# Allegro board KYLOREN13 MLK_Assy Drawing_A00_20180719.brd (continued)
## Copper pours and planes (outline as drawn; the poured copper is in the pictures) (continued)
PWR_CHG_LGATE2 on TOP: 46.1,63.01 45.97,63.14 45.97,63.65 46.1,63.77 47.24,63.77 47.37,63.65 47.37,63.14 47.24,63.01
PWR_CHG_PHASE1 on TOP: 43.18,57.04 42.8,57.42 39.88,57.42 39.75,57.55 39.75,59.84 39.88,59.96 42.29,59.96 42.42,60.09 42.42,62.38 43.81,62.38 44.2,61.99 44.2,57.42 43.81,57.04
PWR_CHG_PHASE1 on BOTTOM: 38.1,56.66 37.97,56.79 37.97,60.22 38.1,60.34 39.75,60.34 41.78,62.38 43.94,62.38 44.2,62.12 44.2,57.42 43.43,56.66
PWR_CHG_PHASE2 on TOP: 45.73,57.41 45.34,57.8 45.34,62.25 45.72,62.63 49.66,62.63 49.91,62.38 49.91,60.09 49.78,59.96 47.5,59.96 47.12,59.58 47.12,57.55 46.98,57.41
PWR_CHG_PHASE2 on BOTTOM: 45.85,56.53 45.34,57.04 45.34,62.5 45.47,62.63 49.02,62.63 49.91,61.74 49.91,56.66 49.78,56.53
PWR_CHG_UGATE1 on TOP: 43.81,62.88 43.69,63.01 43.69,65.42 44.83,65.42 44.96,65.3 44.96,63.14 44.7,62.88
PWR_CHG_VBATIN on BOTTOM: 141.35,13.23 141.1,13.48 141.1,14.24 141.86,15 141.86,19.58 143,19.58 143.38,19.2 143.38,18.18 143.51,18.05 144.27,18.05 144.27,15.64 144.65,15.26 144.65,13.35 144.53,13.23
PWR_DCBATOUT_1D0V on BOTTOM: 169.16,52.6 168.91,52.85 168.53,52.85 168.4,52.98 168.4,55.26 168.53,55.39 169.04,55.39 169.54,55.9 173.23,55.9 173.86,55.26 173.86,54.5 174.12,54.25 175.9,54.25 176.28,54.63 176.28,58.06 176.53,58.31 177.55,58.31 177.67,58.18 177.67,55.26 177.8,55.14 177.8,53.51 176.89,52.6 ; 4 cut-outs
PWR_DCBATOUT_3D3V on BOTTOM: 125.93,22.07 125.91,22.09 125.91,26.48 126.24,26.82 130.56,26.82 130.81,26.56 130.81,23.26 130.18,22.62 127.74,22.62 127.18,22.07 ; 2 cut-outs
PWR_DCBATOUT_5V on BOTTOM: 55.12,15.13 52.58,17.67 52.58,18.18 51.44,19.32 51.44,19.83 51.56,19.96 56.01,19.96 56.13,19.83 56.13,19.7 56.39,19.45 62.23,19.45 62.87,20.08 64.01,20.08 64.14,19.96 64.14,16.91 62.36,15.13 ; 2 cut-outs
PWR_DCBATOUT_VCCGTA on TOP: 58.52,73.2 58.42,73.3 58.42,75.08 58.17,75.33 55.37,75.33 54.1,76.6 54.1,86.38 54.61,86.89 59.05,86.89 59.44,86.51 59.44,82.7 58.55,81.81 58.55,78.76 58.8,78.5 59.18,78.5 59.69,78 59.69,73.3 59.59,73.2
PWR_DCBATOUT_VCCGTA on BOTTOM: 49.53,71.52 49.4,71.65 49.4,75.2 51.18,76.98 51.18,78.89 51.94,79.65 56.64,79.65 56.77,79.52 56.77,78.76 57.02,78.5 59.82,78.5 59.94,78.38 59.94,77.62 59.56,77.23 59.56,75.96 59.61,75.91 59.61,73.27 59.56,73.22 58.52,73.22 58.45,73.3 58.45,74.62 58.29,74.77 56.59,74.77 56.01,74.19 54.23,74.19 53.59,73.55 53.59,72.28 53.09,71.77 50.42,71.77 50.16,71.52 ; 8 cut-outs
PWR_DCBATOUT_VCCGTA on BOTTOM: 58.47,82.42 58.47,83.81 58.37,83.91 57.33,83.91 55.63,85.62 55.63,87.14 55.75,87.27 56.64,87.27 57.15,87.78 57.15,87.9 57.4,88.16 59.31,88.16 59.59,87.88 59.59,82.52 59.49,82.42 ; 11 cut-outs
PWR_DCBATOUT_VCCGTA on L4SGND: 56.26,87.52 58.42,87.52 59.31,86.63 59.31,82.31 59.18,82.19 56.26,82.19 55.63,82.82 55.63,86.89
PWR_DCBATOUT_VCCGTA on L4SGND: 55.88,78.25 58.93,78.25 59.31,77.87 59.31,73.3 59.05,73.04 56.39,73.04 55.5,73.93 55.5,77.87
PWR_DCBATOUT_VCCGTA on L6: 56.39,87.39 58.17,87.39 58.42,87.14 58.42,85.49 58.17,85.24 55.5,85.24 55.12,85.62 55.12,86.12
PWR_DCBATOUT_VCCGTA on L6: 55.75,78.5 57.66,78.5 59.44,76.73 59.44,72.79 59.31,72.66 56.64,72.66 55.37,73.93 55.37,78.12
PWR_DCBATOUT_VCCGTA on L6: 57.28,84.22 59.18,84.22 59.31,84.09 59.31,82.06 59.05,81.81 57.28,81.81 57.15,81.93 57.15,84.09
PWR_DCBATOUT_VCCSA on BOTTOM: 146.3,104.41 146.05,104.67 145.29,104.67 145.03,104.92 142.75,104.92 142.62,105.05 142.62,108.35 142.75,108.48 145.16,108.48 145.29,108.35 145.29,107.21 145.41,107.08 147.19,107.08 147.32,107.21 147.32,107.97 147.45,108.1 147.83,108.1 147.96,107.97 147.96,104.67 147.7,104.41 ; 2 cut-outs
PWR_DCBATOUT_VCORE on TOP: 58.67,61.74 58.55,61.87 58.55,63.77 58.67,63.9 59.44,63.9 59.56,63.77 59.56,61.87 59.44,61.74
PWR_DCBATOUT_VCORE on BOTTOM: 58.52,61.82 58.45,61.89 58.45,63.24 58.34,63.34 56.26,63.34 56.18,63.26 56.01,63.26 55.63,63.65 55.63,66.44 55.37,66.69 54.99,66.69 54.74,66.95 54.74,67.84 54.86,67.96 58.17,67.96 58.55,68.34 60.45,68.34 60.58,68.22 60.58,65.93 59.59,64.94 59.59,61.94 59.46,61.82 ; 10 cut-outs
PWR_DCBATOUT_VCORE on L3SGND: 58.55,63.9 59.31,63.9 59.44,63.77 59.44,61.61 59.18,61.36 58.55,61.36 58.29,61.61 58.29,63.65
PWR_DCBATOUT_VCORE on L4SGND: 59.44,64.15 59.18,64.41 57.4,64.41 57.28,64.28 57.28,61.36 57.53,61.11 59.18,61.11 59.44,61.36
PWR_DCBATOUT_VCORE on L6: 57.4,64.41 59.44,64.41 59.56,64.28 59.56,61.74 59.18,61.36 57.53,61.36 57.28,61.61 57.28,64.28
PWR_DCBATOUT_VDDQ on BOTTOM: 154.05,25.8 153.92,25.93 153.92,26.82 153.42,27.32 152.65,27.32 152.27,27.7 152.27,28.47 152.53,28.72 156.59,28.72 156.84,28.97 156.84,29.48 156.97,29.61 158.5,29.61 158.62,29.48 158.62,27.32 158.5,27.2 156.72,27.2 155.32,25.8 ; 2 cut-outs
PWR_VCCGT_SWA on BOTTOM: 60.96,79.52 60.83,79.65 60.83,80.16 62.1,80.16 62.23,80.28 62.23,84.22 62.36,84.35 66.42,84.35 66.55,84.22 66.55,83.33 66.04,82.82 66.04,80.03 65.53,79.52
PWR_VCCGT_SWB on BOTTOM: 61.21,70 60.83,70.38 60.83,71.14 61.98,71.14 62.23,71.39 62.23,75.08 62.48,75.33 65.79,75.33 66.04,75.08 66.04,70.63 65.41,70
PWR_VCCSA_SW on BOTTOM: 138.94,101.11 138.3,101.75 138.3,104.16 138.43,104.29 138.43,107.84 138.68,108.1 140.21,108.1 141.1,107.21 142.11,107.21 142.24,107.08 142.24,105.05 142.62,104.67 143.89,104.67 144.02,104.54 144.02,101.24 143.89,101.11
PWR_VCORE_SW on TOP: 65.02,60.22 64.9,60.34 64.9,63.26 65.28,63.65 65.91,63.65 66.42,63.14 66.42,60.72 65.91,60.22
PWR_VCORE_SW on BOTTOM: 61.21,58.57 60.83,58.95 60.83,59.71 61.98,59.71 62.23,59.96 62.23,63.65 62.48,63.9 65.79,63.9 66.04,63.65 66.04,59.2 65.41,58.57
PWR_VDDQ_PH on BOTTOM: 149.35,23.39 148.97,23.77 148.97,28.21 149.22,28.47 151.38,28.47 152.91,26.94 152.91,26.51 153.47,25.95 153.47,25.44 153.39,25.37 152.73,25.37 152.02,24.66 152.02,23.89 151.51,23.39
RING2_R on BOTTOM: 5.46,12.72 5.33,12.85 5.33,14.12 4.57,14.88 4.57,16.66 3.3,17.93 3.3,19.32 3.68,19.7 5.21,19.7 5.63,19.28 5.63,17.53 5.84,17.32 5.84,16.27 5.97,16.15 6.48,16.15 6.6,16.02 6.6,15.39 6.22,15 6.22,14.24 6.1,14.12 6.1,12.85 5.97,12.72
SLEEVE_R on BOTTOM: 17.02,25.8 16.89,25.93 16.89,27.07 16.76,27.2 16.38,27.2 15.88,27.7 15.88,28.72 15.62,28.97 13.97,28.97 13.34,29.61 6.22,29.61 5.71,29.1 5.71,28.59 5.43,28.31 2.76,28.31 2.76,29.86 4.19,29.86 4.33,30 4.87,30.25 5.18,30.75 15.77,30.75 17.17,29.36 17.4,29.36 17.91,28.85 17.91,27.96 17.78,27.83 17.78,25.93 17.65,25.8 ; 2 cut-outs
USB_ADT on BOTTOM: 23.37,68.22 23.16,68.42 23.16,70.43 23.29,70.55 23.93,70.55 24.13,70.76 24.13,71.14 24.26,71.27 27.43,71.27 27.56,71.14 27.56,68.85 27.43,68.73 24.64,68.73 24.13,68.22

Small or netless copper shapes (teardrops, artwork), in the pictures only: 1 on TOP

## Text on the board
Ref Des/Silkscreen Bottom: KB | EDP2 | EDP1 | F5503:1.1A/24V | F5701:1.1A/6V | X5701:27MHZ | F6501:1.1A/6V | X2401:32.768KHZ | FPR | IO | BYT | X1801:24MHZ
User.Comments: CR_CPU_CORE_1 | CR_CPU_CORE_2
Ref Des/Silkscreen Top: F5504:1.1A/6V | X1802:32.768KHZ | F5502:1.1A/6V | 17945-1 | 1K5G3 | Kylo Ren 13 CS MLK | MADE IN TAIWAN
User.27: ByImpedance:100.0_DP@_REF_L1=("5.0/4.0(L3)" "3.0/9.0(L2)")|_REF_L6=("3.0/7.5(L5/L7)" "3.5/7.0(L4/L7)")|Type="DP"|_REF_L3=("3.5/7.0(L2/L5)" "3.0/7.5(L2/L4)")|_REF_L4=("3.0/7.5(L3/L5)" "3.5/7.0(L2/L5)")|imp="100.0"|_REF_L5=("3.5/7.0(L4/L7)")|_REF_L8=("3.0/9.0(L7)" "5.0/4.0(L6)") | ByImpedance:27.4_SE@_REF_L1=("11.0(L2)")|_REF_L6=("10.5(L5/L7)" "13.5(L4/L7)")|Type="SE"|_REF_L3=("13.5(L2/L5)" "10.5(L2/L4)")|_REF_L4=("13.5(L2/L5)" "10.5(L3/L5)")|imp="27.4"|_REF_L5=("13.5(L4/L7)")|_REF_L8=("11.0(L7)") | ByImpedance:33.0_SE@_REF_L1=("8.0(L2)")|_REF_L6=("8.1(L5/L7)" "10.0(L4/L7)")|Type="SE"|_REF_L3=("10.0(L2/L5)" "8.1(L2/L4)")|_REF_L4=("10.0(L2/L5)" "8.1(L3/L5)")|imp="33.0"|_REF_L5=("10.0(L4/L7)")|_REF_L8=("8.0(L7)") | ByImpedance:35.0_SE@_REF_L1=("7.5(L2)")|_REF_L6=("7.1(L5/L7)" "9.0(L4/L7)")|Type="SE"|_REF_L3=("9.0(L2/L5)" "7.1(L2/L4)")|_REF_L4=("9.0(L2/L5)" "7.1(L3/L5)")|imp="35.0"|_REF_L5=("9.0(L4/L7)")|_REF_L8=("7.5(L7)") | ByImpedance:37.5_SE@_REF_L1=("6.5(L2)")|_REF_L6=("8.0(L4/L7)" "6.6(L5/L7)")|Type="SE"|_REF_L3=("8.0(L2/L5)" "6.6(L2/L4)")|_REF_L4=("8.0(L2/L5)" "6.6(L3/L5)")|imp="37.5"|_REF_L5=("8.0(L4/L7)")|_REF_L8=("6.5(L7)") | ByImpedance:39.0_SE@_REF_L1=("6.0(L2)")|_REF_L6=("6.1(L5/L7)" "7.5(L4/L7)")|Type="SE"|_REF_L3=("7.5(L2/L5)" "6.1(L2/L4)")|_REF_L4=("6.1(L3/L5)" "7.5(L2/L5)")|imp="39.0"|_REF_L5=("7.5(L4/L7)")|_REF_L8=("6.0(L7)") | ByImpedance:40.0_SE@_REF_L2=("3.5(L1/L3)")|_REF_L1=("5.5(L2)")|_REF_L6=("5.6(L5/L7)" "7.0(L4/L7)")|Type="SE"|_REF_L3=("7.0(L2/L5)" "5.6(L2/L4)")|_REF_L4=("5.6(L3/L5)" "7.0(L2/L5)")|imp="40.0"|_REF_L5=("7.0(L4/L7)")|_REF_L8=("5.5(L7)") | ByImpedance:42.0_SE@_REF_L1=("5.0(L2)")|_REF_L6=("6.5(L4/L7)" "5.1(L5/L7)")|Type="SE"|_REF_L3=("6.5(L2/L5)" "5.1(L2/L4)")|_REF_L4=("5.1(L3/L5)" "6.5(L2/L5)")|imp="42.0"|_REF_L5=("6.5(L4/L7)")|_REF_L8=("5.0(L7)") | ByImpedance:45.0_SE@_REF_L1=("4.5(L2)")|_REF_L6=("5.5(L4/L7)" "4.4(L5/L7)")|Type="SE"|_REF_L3=("5.5(L2/L5)" "4.4(L2/L4)")|_REF_L4=("5.5(L2/L5)" "4.4(L3/L5)")|imp="45.0"|_REF_L5=("5.5(L4/L7)")|_REF_L8=("4.5(L7)") | ByImpedance:48.0_SE@_REF_L1=("4.0(L2)")|_REF_L6=("5.0(L4/L7)" "3.9(L5/L7)")|Type="SE"|_REF_L3=("3.9(L2/L4)" "5.0(L2/L5)")|_REF_L4=("3.9(L3/L5)" "5.0(L2/L5)")|imp="48.0"|_REF_L5=("5.0(L4/L7)")|_REF_L8=("4.0(L7)") | ByImpedance:50.0_DP@_REF_L1=("10.5/4.0(L2)")|_REF_L6=("10.5/4.0(L5/L7)" "13.0/4.0(L4/L7)")|Type="DP"|_REF_L3=("13.0/4.0(L2/L5)" "10.5/4.0(L2/L4)")|_REF_L4=("10.5/4.0(L3/L5)" "13.0/4.0(L2/L5)")|imp="50.0"|_REF_L5=("13.0/4.0(L4/L7)")|_REF_L8=("10.5/4.0(L7)") | ByImpedance:50.0_SE@_REF_L1=("3.5(L2)")|_REF_L6=("4.5(L4/L7)" "3.5(L5/L7)")|Type="SE"|_REF_L3=("3.5(L2/L4)" "4.5(L2/L5)")|_REF_L4=("3.5(L3/L5)" "4.5(L2/L5)")|imp="50.0"|_REF_L5=("4.5(L4/L7)")|_REF_L8=("3.5(L7)") | ByImpedance:55.0_SE@_REF_L6=("3.51(L4/L7)")|Type="SE"|_REF_L3=("3.51(L2/L5)")|_REF_L4=("3.51(L2/L5)")|imp="55.0"|_REF_L5=("3.51(L4/L7)") | ByImpedance:68.0_DP@_REF_L1=("6.5/5.0(L2)")|_REF_L6=("7.0/4.0(L4/L7)" "6.5/5.0(L5/L7)")|Type="DP"|_REF_L3=("6.5/5.0(L2/L4)" "7.0/4.0(L2/L5)")|_REF_L4=("7.0/4.0(L2/L5)" "6.5/5.0(L3/L5)")|imp="68.0"|_REF_L5=("7.0/4.0(L4/L7)")|_REF_L8=("6.5/5.0(L7)") | ByImpedance:70.0_DP@_REF_L1=("6.0/5.0(L2)")|_REF_L6=("6.5/4.0(L4/L7)" "6.0/5.0(L5/L7)")|Type="DP"|_REF_L3=("6.0/5.0(L2/L4)" "6.5/4.0(L2/L5)")|_REF_L4=("6.0/5.0(L3/L5)" "6.5/4.0(L2/L5)")|imp="70.0"|_REF_L5=("6.5/4.0(L4/L7)")|_REF_L8=("6.0/5.0(L7)") | ByImpedance:72.0_DP@_REF_L2=("4.0/5.0(L1/L3)")|_REF_L1=("5.5/5.0(L2)")|_REF_L6=("5.4/4.0(L5/L7)" "6.0/4.0(L4/L7)")|Type="DP"|_REF_L3=("5.4/4.0(L2/L4)" "6.0/4.0(L2/L5)")|_REF_L4=("5.4/4.0(L3/L5)" "6.0/4.0(L2/L5)")|imp="72.0"|_REF_L5=("6.0/4.0(L4/L7)")|_REF_L8=("5.5/5.0(L7)") | ByImpedance:75.0_DP@_REF_L1=("5.0/5.0(L2)")|_REF_L6=("5.0/4.0(L5/L7)" "5.5/4.0(L4/L7)")|Type="DP"|_REF_L3=("5.5/4.0(L2/L5)" "5.0/4.0(L2/L4)")|_REF_L4=("5.5/4.0(L2/L5)" "5.0/4.0(L3/L5)")|imp="75.0"|_REF_L5=("5.5/4.0(L4/L7)")|_REF_L8=("5.0/5.0(L7)") | ByImpedance:80.0_DP@_REF_L1=("5.0/7.0(L2)" "4.5/5.0(L2)")|_REF_L6=("4.4/4.5(L5/L7)" "4.5/4.0(L4/L7)")|Type="DP"|_REF_L3=("4.5/4.0(L2/L5)" "4.4/4.5(L2/L4)")|_REF_L4=("4.5/4.0(L2/L5)" "4.4/4.5(L3/L5)")|imp="80.0"|_REF_L5=("4.5/4.0(L4/L7)")|_REF_L8=("4.5/5.0(L7)" "5.0/7.0(L7)") | ByImpedance:83.0_DP@_REF_L1=("3.5/4.0(L2)")|_REF_L6=("4.0/4.5(L5/L7)" "4.5/4.5(L4/L7)")|Type="DP"|_REF_L3=("4.0/4.5(L2/L4)" "4.5/4.5(L2/L5)")|_REF_L4=("4.0/4.5(L3/L5)" "4.5/4.5(L2/L5)")|imp="83.0"|_REF_L5=("4.5/4.5(L4/L7)")|_REF_L8=("3.5/4.0(L7)") | ByImpedance:85.0_DP@_REF_L2=("3.0/7.0(L1/L3)")|_REF_L1=("9.0/4.0(L3)" "4.0/5.0(L2)")|_REF_L6=("4.0/4.0(L4/L7)" "3.5/4.0(L5/L7)")|Type="DP"|_REF_L3=("3.5/4.0(L2/L4)" "4.0/4.0(L2/L5)")|_REF_L4=("3.5/4.0(L3/L5)" "4.0/4.0(L2/L5)")|imp="85.0"|_REF_L5=("4.0/4.0(L4/L7)")|_REF_L8=("9.0/4.0(L6)" "4.0/5.0(L7)") | ByImpedance:90.0_DP@_REF_L1=("4.0/8.0(L2)" "7.5/4.0(L3)")|_REF_L6=("3.5/5.0(L5/L7)" "3.5/4.5(L4/L7)")|Type="DP"|_REF_L3=("3.5/5.0(L2/L4)" "3.5/4.5(L2/L5)")|_REF_L4=("3.5/4.5(L2/L5)" "3.5/5.0(L3/L5)")|imp="90.0"|_REF_L5=("3.5/4.5(L4/L7)")|_REF_L8=("7.5/4.0(L6)" "4.0/8.0(L7)") | ByImpedance:95.0_DP@_REF_L1=("6.0/4.0(L3)" "3.5/9.0(L2)")|_REF_L6=("3.5/8.0(L5/L7)" "3.5/5.5(L4/L7)")|Type="DP"|_REF_L3=("3.5/8.0(L2/L4)" "3.5/5.5(L2/L5)")|_REF_L4=("3.5/5.5(L2/L5)" "3.5/8.0(L3/L5)")|imp="95.0"|_REF_L5=("3.5/5.5(L4/L7)")|_REF_L8=("3.5/9.0(L7)" "6.0/4.0(L6)") | LayerIndex:nil | Source:8-1.0-15k.xls | artWorks:("_REF_L4" "_REF_L6" "_REF_L5" "_REF_L3" "_REF_L8" "_REF_L1" "_REF_L2") | gtImpOutlineUsed:BOARD GEOMETRY/PANEL_OUTLINE
User.35: Board Accuracy Check,Jul 19 14:14:02 2018,Passed | Dummy-Static-No Shape On Layer Check,Jul 19 14:14:04 2018,Passed | Split Plane Check,Jul 19 14:14:02 2018,Passed
User.39: This gerber is just for your reference to find the DP impedance traces in layer L1. | DP IMPEDANCE TABLE: L1 | * - Denotes that this Impedance | is NOT used | IMP(Ohm) | *50.0 | *68.0 | *70.0 | *72.0 | *75.0 | *80.0 | *83.0 | *85.0 | 85.0 | *90.0 | *95.0 | *100.0 | 100.0 | WIDTH(mils) | 10.5/4.0 | 6.5/5.0 | 6.0/5.0 | 5.5/5.0 | 5.0/5.0 | 5.0/7.0 | 4.5/5.0 | 3.5/4.0 | 9.0/4.0 | 4.0/5.0 | 4.0/8.0 | 7.5/4.0 | 6.0/4.0 | 3.5/9.0 | 5.0/4.0 | 3.0/9.0 | TYPE | DP | Ref. Plane | L2 | L3
User.41: This gerber is just for your reference to find the SE impedance traces in layer L1. | SE IMPEDANCE TABLE: L1 | * - Denotes that this Impedance | is NOT used | IMP(Ohm) | *27.4 | *33.0 | *35.0 | *37.5 | *39.0 | 40.0 | *42.0 | *45.0 | *48.0 | 50.0 | WIDTH(mils) | 11.0 | 8.0 | 7.5 | 6.5 | 6.0 | 5.5 | 5.0 | 4.5 | 4.0 | 3.5 | TYPE | SE | Ref. Plane | L2
User.43: This gerber is just for your reference to find the DP impedance traces in layer L2. | DP IMPEDANCE TABLE: L2 | * - Denotes that this Impedance | is NOT used | IMP(Ohm) | *72.0 | *85.0 | WIDTH(mils) | 4.0/5.0 | 3.0/7.0 | TYPE | DP | Ref. Plane | L1/L3
User.45: Note:Refer to DRILL layer for ELLIPSE drill direction | FIGURE | SIZE | 10.0 | 16.0 | 18.0 | 22.0 | 28.0 | 113.0 | 150.0 | 178.0 | 30.0 | 38.0 | 46.0 | 65.0 | 71.0 | 86.0 | 99.0 | 158.0 | 40.0x20.0 | 44.0x20.0 | 60.0x24.0 | 60.0x36.0 | 63.0x24.0 | 67.0x36.0 | 69.0x20.0 | 90.0x28.0 | DRILL CHART: TOP to BOTTOM | ALL UNITS ARE IN MILS | PLATED | NON-PLATED | QTY | 3843 | 466 | 10 | 33 | 19 | 9 | 1 | 4 | 5 | 2 | 8 | 7 | This gerber is just for your reference to find the DP impedance traces in layer L3. | This gerber is just for your reference to find the DP impedance traces in layer L4. | This gerber is just for your reference to find the DP impedance traces in layer L5. | This gerber is just for your reference to find the DP impedance traces in layer L6. | This gerber is just for your reference to find the DP impedance traces in layer L8. | This gerber is just for your reference to find the SE impedance traces in layer L2. | This gerber is just for your reference to find the SE impedance traces in layer L3. | This gerber is just for your reference to find the SE impedance traces in layer L4. | This gerber is just for your reference to find the SE impedance traces in layer L5. | This gerber is just for your reference to find the SE impedance traces in layer L6. | This gerber is just for your reference to find the SE impedance traces in layer L8. | DP IMPEDANCE TABLE: L3 | DP IMPEDANCE TABLE: L4 | DP IMPEDANCE TABLE: L5 | DP IMPEDANCE TABLE: L6 | DP IMPEDANCE TABLE: L8 | SE IMPEDANCE TABLE: L2 | SE IMPEDANCE TABLE: L3 | SE IMPEDANCE TABLE: L4 | SE IMPEDANCE TABLE: L5 | SE IMPEDANCE TABLE: L6 | SE IMPEDANCE TABLE: L8 | * - Denotes that this Impedance | is NOT used | Model | Kylo Ren 13 CS MLK | PCB_NO | 17945 | VER. | Layer | DRILL | L1 | L2SGND | L3SGND | L4SGND | TMASK | TPLACE | TSILK | TSMD | Designer | BARLEN LIU | IMP(Ohm) | *27.4 | *50.0 | 40.0 | *33.0 | *68.0 | *35.0 | *70.0 | *37.5 | *72.0 | *39.0 | *75.0 | *40.0 | *80.0 | *42.0 | *83.0 | 72.0 | *45.0 | *85.0 | *48.0 | *90.0 | *95.0 | 50.0 | 85.0 | *100.0 | *55.0 | 100.0 | Date | 07/19/2018 | WIDTH(mils) | 11.0 | 3.5 | 8.0 | 7.5 | 6.5 | 6.0 | 5.5 | 5.0 | 4.5 | 4.0 | 10.5 | 13.5 | 8.1 | 9.0 | 7.1 | 7.0 | 6.6 | 6.1 | 3.51 | 5.6 | 5.1 | 4.4 | 3.9 | 10.5/4.0 | 6.5/5.0 | 6.0/5.0 | 5.5/5.0 | 5.0/5.0 | 4.5/5.0 | 5.0/7.0 | 3.5/4.0 | 9.0/4.0 | 4.0/5.0 | 7.5/4.0 | 4.0/8.0 | 3.5/9.0 | 6.0/4.0 | 3.0/9.0 | 5.0/4.0 | 13.0/4.0 | 7.0/4.0 | 6.5/4.0 | 5.5/4.0 | 4.5/4.0 | 4.5/4.5 | 5.4/4.0 | 4.0/4.0 | 3.5/4.5 | 3.5/5.5 | 3.5/7.0 | 4.4/4.5 | 4.0/4.5 | 3.5/5.0 | 3.5/8.0 | 3.0/7.5 | TYPE | SE | DP | Ref. Plane | L1/L3 | L7 | L2/L5 | L4/L7 | L5/L7 | L2/L4 | L3/L5 | L6 | BMASK | BPLACE | BSILK | BSMD | L5GND | L7GND | L8
